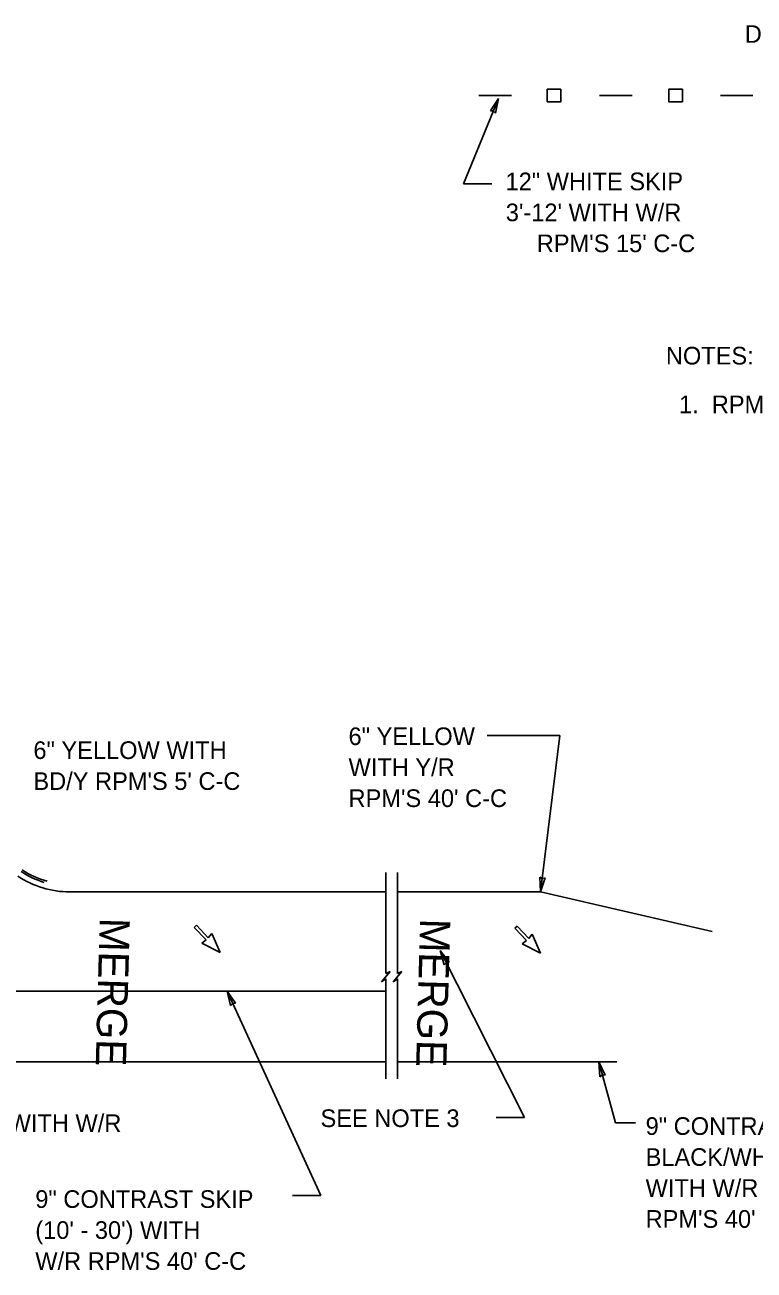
# Model space of a CAD drawing. Extents: x 583689 to 590775, y 1496016 to 1497365.
# Drawn here: x 587896.7 to 588186, y 1496193.2 to 1496686.9 of the extents above; entities that cross this region are included whole.
import ezdxf

# ---------------------------------------------------------------- set-up
doc = ezdxf.new("R2010")
doc.units = 0
for name, color, linetype in [('2', 7, 'Continuous'), ('20', 7, 'Continuous'), ('21', 7, 'Continuous'), ('24', 7, 'Continuous'), ('32', 7, 'Continuous'), ('50', 7, 'Continuous'), ('52', 7, 'Continuous'), ('TextNotes', 7, 'Continuous')]:
    doc.layers.add(name, color=color, linetype=linetype)

msp = doc.modelspace()

# ---------------------------------------------------------------- linework, layer by layer
at = {"layer": '2'}
for p, q in [((587914.46, 1496343.13), (588039.9, 1496343.13)), ((588044.46, 1496343.13), (588101.26, 1496343.13)), ((588101.26, 1496343.13), (588169.33, 1496327.49)), ((587813.57, 1496303.79), (588039.9, 1496303.8)), ((587663.57, 1496275.75), (588039.9, 1496275.75)), ((588044.46, 1496275.75), (588131.47, 1496275.75))]:
    msp.add_line(p, q, dxfattribs=at)
for radius, end in [(35.25, 253.0681), (34.5, 254.5578), (37.5, 269.7206)]:
    msp.add_arc((587914.65, 1496380.63), radius, 236.4357, end, dxfattribs=at)
at = {"layer": '20'}
for p, q in [((587964.79, 1496329.9), (587963.89, 1496329.04)), ((587969.44, 1496325), (587964.79, 1496329.9)), ((587963.89, 1496329.04), (587968.53, 1496324.14)), ((587970.83, 1496326.63), (587969.44, 1496325)), ((587974.15, 1496319.13), (587970.83, 1496326.63)), ((588091.9, 1496329.59), (588091, 1496328.73)), ((588091, 1496328.73), (588095.64, 1496323.84)), ((588096.55, 1496324.7), (588091.9, 1496329.59)), ((588097.94, 1496326.33), (588096.55, 1496324.7)), ((588101.26, 1496318.83), (588097.94, 1496326.33)), ((587968.53, 1496324.14), (587966.84, 1496322.84)), ((587966.84, 1496322.84), (587974.15, 1496319.13)), ((588095.64, 1496323.84), (588093.95, 1496322.54)), ((588093.95, 1496322.54), (588101.26, 1496318.83))]:
    msp.add_line(p, q, dxfattribs=at)
at = {"layer": '21'}
for p, q in [((588108.87, 1496405.11), (588080.02, 1496405.16)), ((588101.26, 1496343.13), (588108.87, 1496405.11)), ((588039.9, 1496350.84), (588039.9, 1496310.79)), ((588044.46, 1496350.84), (588044.46, 1496310.79)), ((588061.46, 1496319.93), (588094.84, 1496253.66)), ((588041.64, 1496311.58), (588038.17, 1496307.48)), ((588039.9, 1496310.79), (588041.64, 1496311.58)), ((588046.19, 1496311.58), (588042.73, 1496307.48)), ((588044.46, 1496310.79), (588046.19, 1496311.58)), ((588038.17, 1496307.48), (588039.9, 1496308.74)), ((588039.9, 1496308.74), (588039.9, 1496269.01)), ((588042.73, 1496307.48), (588044.46, 1496308.74)), ((588044.46, 1496308.74), (588044.46, 1496269.01)), ((587976.89, 1496303.8), (588014.09, 1496222.75)), ((588130.93, 1496251.6), (588124.36, 1496275.75)), ((588083.63, 1496253.66), (588094.84, 1496253.66)), ((588138.85, 1496251.58), (588130.93, 1496251.6)), ((588002.88, 1496222.75), (588014.09, 1496222.75))]:
    msp.add_line(p, q, dxfattribs=at)
at = {"layer": '32'}
for p, q in [((588089.69, 1496658.93), (588076.79, 1496658.93)), ((588137.59, 1496658.93), (588124.69, 1496658.93)), ((588185.48, 1496658.93), (588172.59, 1496658.93))]:
    msp.add_line(p, q, dxfattribs=at)
for points in [[(588109.31, 1496661.4), (588103.87, 1496661.4), (588103.87, 1496656.46), (588109.31, 1496656.46)], [(588157.55, 1496661.4), (588152.11, 1496661.4), (588152.11, 1496656.46), (588157.55, 1496656.46)]]:
    msp.add_lwpolyline(points, close=True, dxfattribs=at)
at = {"layer": '50'}
for p, q in [((588070.62, 1496623.86), (588084.54, 1496657.73)), ((588081.9, 1496623.86), (588070.62, 1496623.86))]:
    msp.add_line(p, q, dxfattribs=at)
at = {"layer": '52'}
for p, q in [((588081.34, 1496652.77), (588084.54, 1496657.73)), ((588084.54, 1496657.73), (588083.37, 1496651.94)), ((588082.51, 1496652.77), (588081.34, 1496652.77)), ((588083.37, 1496651.94), (588082.51, 1496652.77)), ((588101.92, 1496348.45), (588100.9, 1496349.02)), ((588100.9, 1496349.02), (588101.26, 1496343.13)), ((588101.26, 1496343.13), (588103.08, 1496348.75)), ((588103.08, 1496348.75), (588101.92, 1496348.45)), ((588061.46, 1496319.93), (588063.07, 1496314.25)), ((588065.04, 1496315.24), (588061.46, 1496319.93)), ((588063.07, 1496314.25), (588063.88, 1496315.14)), ((588063.88, 1496315.14), (588065.04, 1496315.24)), ((587976.89, 1496303.8), (587978.29, 1496298.06)), ((587980.29, 1496298.97), (587976.89, 1496303.8)), ((587978.29, 1496298.06), (587979.13, 1496298.92)), ((587979.13, 1496298.92), (587980.29, 1496298.97)), ((588124.36, 1496275.75), (588124.8, 1496269.86)), ((588126.93, 1496270.44), (588124.36, 1496275.75)), ((588124.8, 1496269.86), (588125.77, 1496270.58)), ((588125.77, 1496270.58), (588126.93, 1496270.44))]:
    msp.add_line(p, q, dxfattribs=at)

# ---------------------------------------------------------------- texts
at = {"layer": '21'}
for s, p in [('6" YELLOW', (588025.07, 1496401.36)), ('6" YELLOW WITH', (587900.05, 1496395.85)), ('WITH Y/R', (588025.07, 1496389.08)), ("BD/Y RPM'S 5' C-C", (587900.05, 1496383.58)), ("RPM'S 40' C-C", (588025.07, 1496376.8)), ('SEE NOTE 3', (588013.96, 1496249.92)), ('9" CONTRAST BLACK/WHITE WITH W/R', (587758.97, 1496247.96)), ('9" CONTRAST', (588142.92, 1496246.8)), ('BLACK/WHITE', (588142.92, 1496234.52)), ('WITH W/R', (588142.92, 1496222.24)), ('9" CONTRAST SKIP', (587900.8, 1496217.86)), ("RPM'S 40' C-C", (588142.92, 1496209.97)), ("(10' - 30') WITH", (587900.8, 1496205.58)), ("W/R RPM'S 40' C-C", (587900.8, 1496193.3))]:
    msp.add_text(s, height=7, dxfattribs=at).set_placement(p)
at = {"layer": '24'}
for p in [(587926.36, 1496332.98), (588053.47, 1496332.67)]:
    msp.add_text('MERGE', height=11.999, rotation=268.4419, dxfattribs=at).set_placement(p)
at = {"layer": '50'}
for s, p in [("DELINEATORS 10' C-C ", (588182.26, 1496679.8)), ('12" WHITE SKIP ', (588087.36, 1496621.36)), ("3'-12' WITH W/R ", (588087.46, 1496609.08)), ("RPM'S 15' C-C", (588099.74, 1496596.8))]:
    msp.add_text(s, height=7, dxfattribs=at).set_placement(p)
at = {"layer": 'TextNotes'}
for s, p in [('NOTES:', (588150.97, 1496552.26)), ("  1.  RPM'S SHALL BE PLACED PER DETAILS D AND E.", (588150.97, 1496532.95))]:
    msp.add_text(s, height=7, dxfattribs=at).set_placement(p)

doc.saveas('drawing.dxf')
